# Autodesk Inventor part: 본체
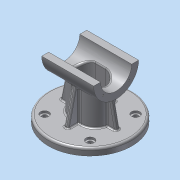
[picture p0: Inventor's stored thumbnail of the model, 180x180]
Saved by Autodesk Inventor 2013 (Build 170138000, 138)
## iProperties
Created: 2015-12
Part Number: 본체
Material: 알루미늄 6061
Document SubType Name: Modeling
Designer: mduedu
Density: 2.71 g/cm^3
Author: mduedu
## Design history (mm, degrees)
sketch "스케치1"
  geometry: L1 (45, 40)-(-45, 40); L2 (-45, 40)-(-45, -40); L3 (-45, -40)-(45, -40); L4 (45, -40)-(45, 40); L5 (45, 40)-(-45, -40); L6 (-45, 40)-(45, -40); 2 further points
  constraints: 12 end point, 2 midpoint, 2 parallel, 1 coincident, 1 horizontal, 1 perpendicular, 3 other
  dimensions: "d0" = 90 distance of L2.end L3.end; "d2" = 80 distance of L1.end L2.end
extrude "돌출1" new body sketch "스케치1" distance "d3" = 10; taper "d4" = 0 deg
sketch "스케치2"
  geometry: C1 r 32.5 at (80, 0); 1 further point
  constraints: 1 centre point
  dimensions: "d5" = 65 diameter of C1; "d116" = 80 distance of point (0, 0) C1.centre
extrude "돌출2" join sketch "스케치2" stored distance "d7" = 75; taper "d8" = 0 deg
sketch "스케치3"
  geometry: L1 (-27.5, -20)-(27.5, -20); L2 (27.5, -20)-(27.5, 20); L3 (27.5, 20)-(-27.5, 20); L4 (-27.5, 20)-(-27.5, -20); L5 (-27.5, -20)-(27.5, 20); L6 (27.5, -20)-(-27.5, 20); 1 further point
  constraints: 12 end point, 2 midpoint, 2 parallel, 1 horizontal, 1 perpendicular
  dimensions: "d9" = 55 distance of L2.end L3.end; "d11" = 40 distance of L1.end L2.end
extrude "돌출3" new body sketch "스케치3" stored distance "d12" = 75; taper "d13" = 0 deg
fillet "모깎기1"
fillet "모깎기2"
feature "결합1"
  node "솔리드2"
sketch "스케치4"
  geometry: L1 (-37.5, 47.5)-(37.5, 47.5) reference; L2 (32.5, 47.5)-(40.208, 10); L3 (37.5, 47.5)-(37.5, 112.5) reference; L4 (60.208, 0)-(60.208, 10) reference; L5 (60.208, 10)-(-60.208, 10) reference; 1 further point
  constraints: 2 end point, 2 point on line
  dimensions: "d15" = 5 distance from line of L2.start L3; "d117" = 20 distance from line of L2.end L4
sketch "스케치5"
  geometry: L1 (10, 35.208)-(58.179, 24.085); L2 (0, 60.208)-(10, 60.208) reference; L3 (10, -60.208)-(10, 60.208) reference; 2 further points
  constraints: 2 end point, 1 point on line, 2 other
  dimensions: "d118" = 25 distance from line of L1.start L2; "d119" = 77 deg angle of L1 L3
feature "리브1" dims "d19" = 1, "d20" = 6, "d21" = 0, "d22" = 0, "d23" = 1, "d24" = 1
feature "리브2" dims "d25" = 1, "d26" = 6, "d27" = 0, "d28" = 0, "d29" = 1, "d30" = 1
fillet "모깎기4" dims "d31" = 2
fillet "모깎기5" dims "d32" = 2
fillet "모깎기16" dims "d149" = 2
sketch "스케치6"
  geometry: L1 (0, 0)-(-32.88, 32.88); L2 (0, 0)-(-46.5, 0); A1 r 46.5 centre (0, 0) between (-32.88, 32.88) and (-46.5, 0); 5 further points
  constraints: 4 end point, 2 coincident, 2 point on circle, 1 centre point, 1 horizontal, 5 other
  dimensions: "d120" = 93 diameter of A1; "d122" = 45 deg angle of L1 L2; "d126" = 360 deg dimension on point (0, 0) point (-32.88, 32.88) (derived)
hole "구멍1" sketch "스케치6" at (-32.88, 32.88), (-32.88, -32.88), (32.88, -32.88), (32.88, 32.88) diameter "d34" = 7; stored, may be unused: countersink angle "d38" = 90 deg, drill point angle "d40" = 118 deg; dims "d35" = 6, "d36" = 12, "d37" = 3, "d39" = 8
fillet "모깎기13" dims "d131" = 3
hole "구멍2" diameter "d44" = 45; stored, may be unused: countersink angle "d48" = 90 deg, drill point angle "d50" = 118 deg; dims "d42" = 10, "d43" = 10, "d45" = 6, "d46" = 4, "d47" = 2, "d49" = 8
sketch "스케치7" dims "d52" = 26.5
  geometry: L1 (0, 0)-(32.5, 0); L2 (0, 0)-(22.981, 22.981); A1 r 32.5 centre (0, 0) between (32.5, 0) and (22.981, 22.981) reference; 3 further points
  constraints: 4 end point, 2 point on circle, 1 coincident, 1 horizontal, 1 point on line, 3 other
  dimensions: "d51" = 45 deg angle of L2 L1
hole "구멍3" sketch "스케치7" at (18.738, 18.738) diameter "d54" = 2.459; stored, may be unused: countersink angle "d58" = 90 deg, drill point angle "d60" = 118 deg; dims "d55" = 8, "d56" = 4, "d57" = 2, "d59" = 10
sketch "스케치9"
  geometry: L1 (-75, 82.5)-(75, 82.5); L2 (75, 82.5)-(75, 0); L3 (75, 0)-(-75, 0); L4 (-75, 0)-(-75, 82.5); C1 r 32.5 at (0, 0) reference; 2 further points
  constraints: 8 end point, 2 parallel, 1 coincident, 1 horizontal, 1 midpoint, 1 perpendicular
  dimensions: "d71" = 50 distance edge to line of C1 L1; "d148" = 150 distance of L1.start L1.end
extrude "돌출5" cut sketch "스케치9" stored distance "d73" = 0; taper "d74" = 0 deg
node "작업 평면1"
sketch "스케치10"
  geometry: L1 (-7.5, 15)-(7.5, 15); L2 (-7.5, -15)-(7.5, -15); A1 r 15 centre (-7.5, 0) between (-7.5, 15) and (-7.5, -15); A2 r 15 centre (7.5, 0) between (7.5, -15) and (7.5, 15); A3 r 20 centre (-7.5, 0) between (-7.5, 20) and (-26.977, 4.545) reference; A4 r 20 centre (7.5, 0) between (26.977, 4.545) and (7.5, 20) reference; 1 further point
  constraints: 7 point on circle, 4 end point, 4 tangent, 3 point on line, 2 centre point, 2 horizontal, 1 concentric
  dimensions: "d150" = 5 radial gap between concentric circles of A1 A3; "d151" = 5 radial gap between concentric circles of A2 A4
extrude "돌출6" cut sketch "스케치10" stored distance "d78" = 50; taper "d79" = 0 deg
fillet "모깎기10" dims "d80" = 3
sketch "스케치11"
  geometry: 2 further points
  constraints: 1 coincident
hole "구멍4" sketch "스케치11" at (0, 0) diameter "d81" = 11; stored, may be unused: countersink angle "d85" = 90 deg, drill point angle "d87" = 118 deg; dims "d82" = 8, "d83" = 40, "d84" = 10, "d86" = 10
sketch "스케치12"
  geometry: C1 r 12 at (0, 0); 1 further point
  constraints: 1 centre point, 1 coincident
  dimensions: "d88" = 24 diameter of C1
extrude "돌출7" cut sketch "스케치12" distance "d89" = 5; taper "d90" = 0 deg
chamfer "모따기1" distance "d91" = 1; stored, may be unused: second distance "d92" = 2, angle "d93" = 45 deg
fillet "모깎기11" dims "d94" = 0.5
fillet "모깎기12" dims "d115" = 0.3
node "작업 평면3"
sketch "스케치17"
  geometry: 2 further points
  constraints: 1 horizontal alignment, 1 other
  dimensions: "d154" = 3.5 distance of point (-3.5, 0) point (0, 0)
feature "엠보싱1" sketch "스케치17" dims "d155" = 0.5, "d156" = 0
node "솔리드1"
mirror "대칭1"
mirror "대칭2"
pattern_circular "원형 패턴1" dims angle "d62" = 360 deg
mirror "대칭3"
